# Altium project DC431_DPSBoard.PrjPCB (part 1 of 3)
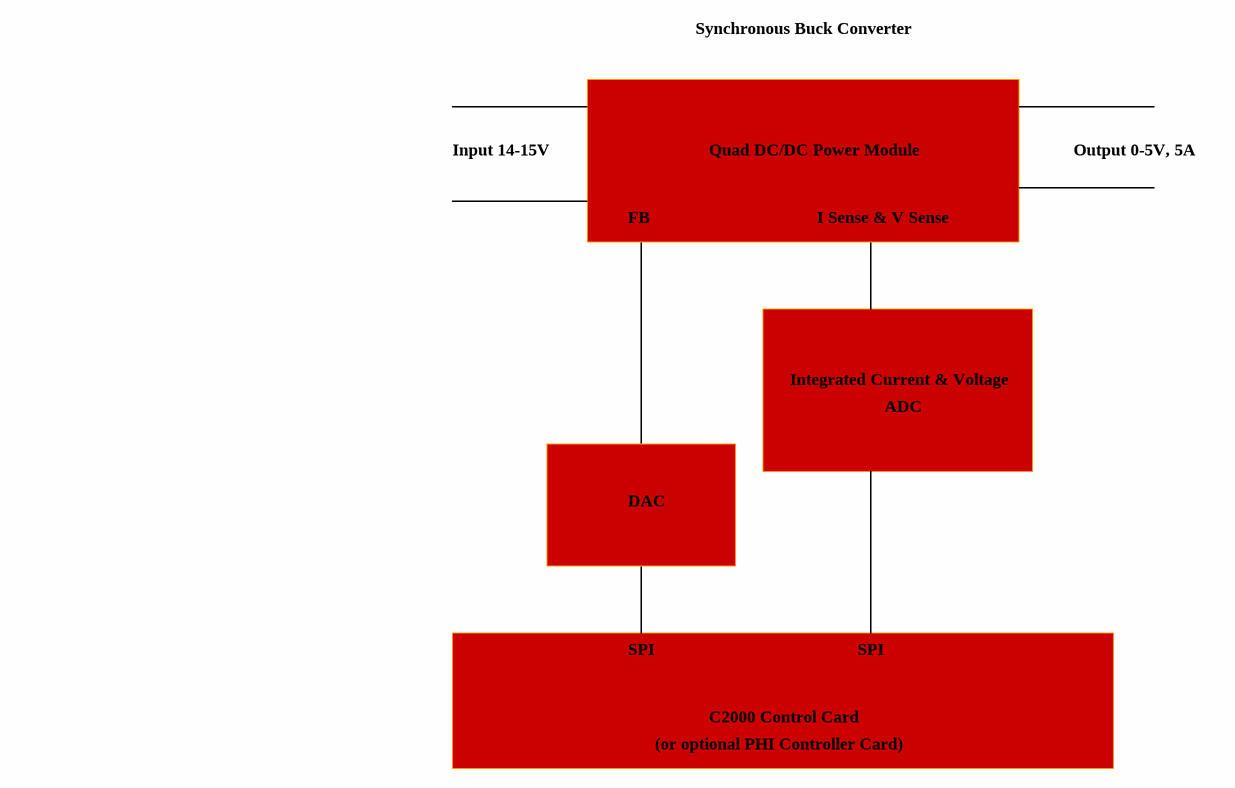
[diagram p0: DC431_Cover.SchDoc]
CopyrightYear: 2025; PCB_Layout: Samiha Sharif; PCB_Rev: A; PRJ_Customer: Public Release; PRJ_Engineer: Samiha Sharif; PRJ_Number: DC431; PRJ_Title: DPS Board; SCH_Rev: A; TechSupport: http://www.ti.com/support; TID: N/A
9 sheets, 455 parts. Net scope: hierarchical (ports join the sheet entries above them; power ports are global).
Board file: SR130E1_pcb.PcbDoc
Sheets:
  DC431_Cover.SchDoc
  DC431_TopLevel.SchDoc
    U_DC431_BiasPower = DC431_BiasPower.SchDoc
    U_DC431_Hardware = DC431_Hardware.SchDoc
    U_DC431_Relay = DC431_Relay.SchDoc
    U_DC431_ADC = DC431_ADC.SchDoc
    U_DC431_Controller = DC431_Controller.SchDoc
    U_DC431_PowerStage = DC431_PowerStage.SchDoc
    U_DC431_Clamp_Optional = DC431_Clamp_Optional.SchDoc

## Sheet DC431_Cover.SchDoc
size 431 x 279 mm; Date: Not shown in title block; ApprovedBy: Not shown in title block; CheckedBy: Not shown in title block; Author: Not shown in title block; CompanyName: Not shown in title block; Engineer: Not shown in title block; Organization: Not shown in title block; Address1: Not shown in title block; Address2: Not shown in title block; Address3: Not shown in title block; Address4: Not shown in title block; DocumentNumber: 1; Revision: Use project parameter SCH_Rev; SheetNumber: 1; SheetTotal: 9; PageSetup: Record=PageOptions¦CenterHorizontal=True¦CenterVertical=True¦PrintScale=1.00¦XCorrection=1.00¦YCorrection=1.00¦PrintKind=0¦BorderSize=5000000¦LeftOffset=0¦BottomOffset=0¦Orientation=2¦PaperLength=1000¦PaperWidth=1000¦Scale=100¦PaperSource=15¦PrintQuality=600¦MediaType=1¦DitherType=10¦PaperKind=Letter¦PrintScaleMode=1

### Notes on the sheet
- Synchronous Buck Converter
- Input 14-15V
- Quad DC/DC Power Module
- Power Stage
- Output 0-5V, 5A
- FB
- I Sense & V Sense
- Integrated Current & Voltage
- ADC
- DAC
- SPI
- (or optional PHI Controller Card)
- C2000 Control Card

## Sheet DC431_TopLevel.SchDoc
size 431 x 279 mm; Date: Not shown in title block; ApprovedBy: Not shown in title block; CheckedBy: Not shown in title block; Author: Not shown in title block; CompanyName: Not shown in title block; DrawnBy: Battery test; Engineer: Not shown in title block; Organization: Not shown in title block; Address1: Not shown in title block; Address2: Not shown in title block; Address3: Not shown in title block; Address4: Not shown in title block; DocumentNumber: 2; Revision: Use project parameter SCH_Rev; SheetNumber: 2; SheetTotal: 9; PageSetup: Record=PageOptions¦CenterHorizontal=True¦CenterVertical=True¦PrintScale=1.00¦XCorrection=1.00¦YCorrection=1.00¦PrintKind=0¦BorderSize=5000000¦LeftOffset=0¦BottomOffset=0¦Orientation=2¦PaperLength=1000¦PaperWidth=1000¦Scale=100¦PaperSource=15¦PrintQuality=600¦MediaType=1¦DitherType=10¦PaperKind=Letter¦PrintScaleMode=1
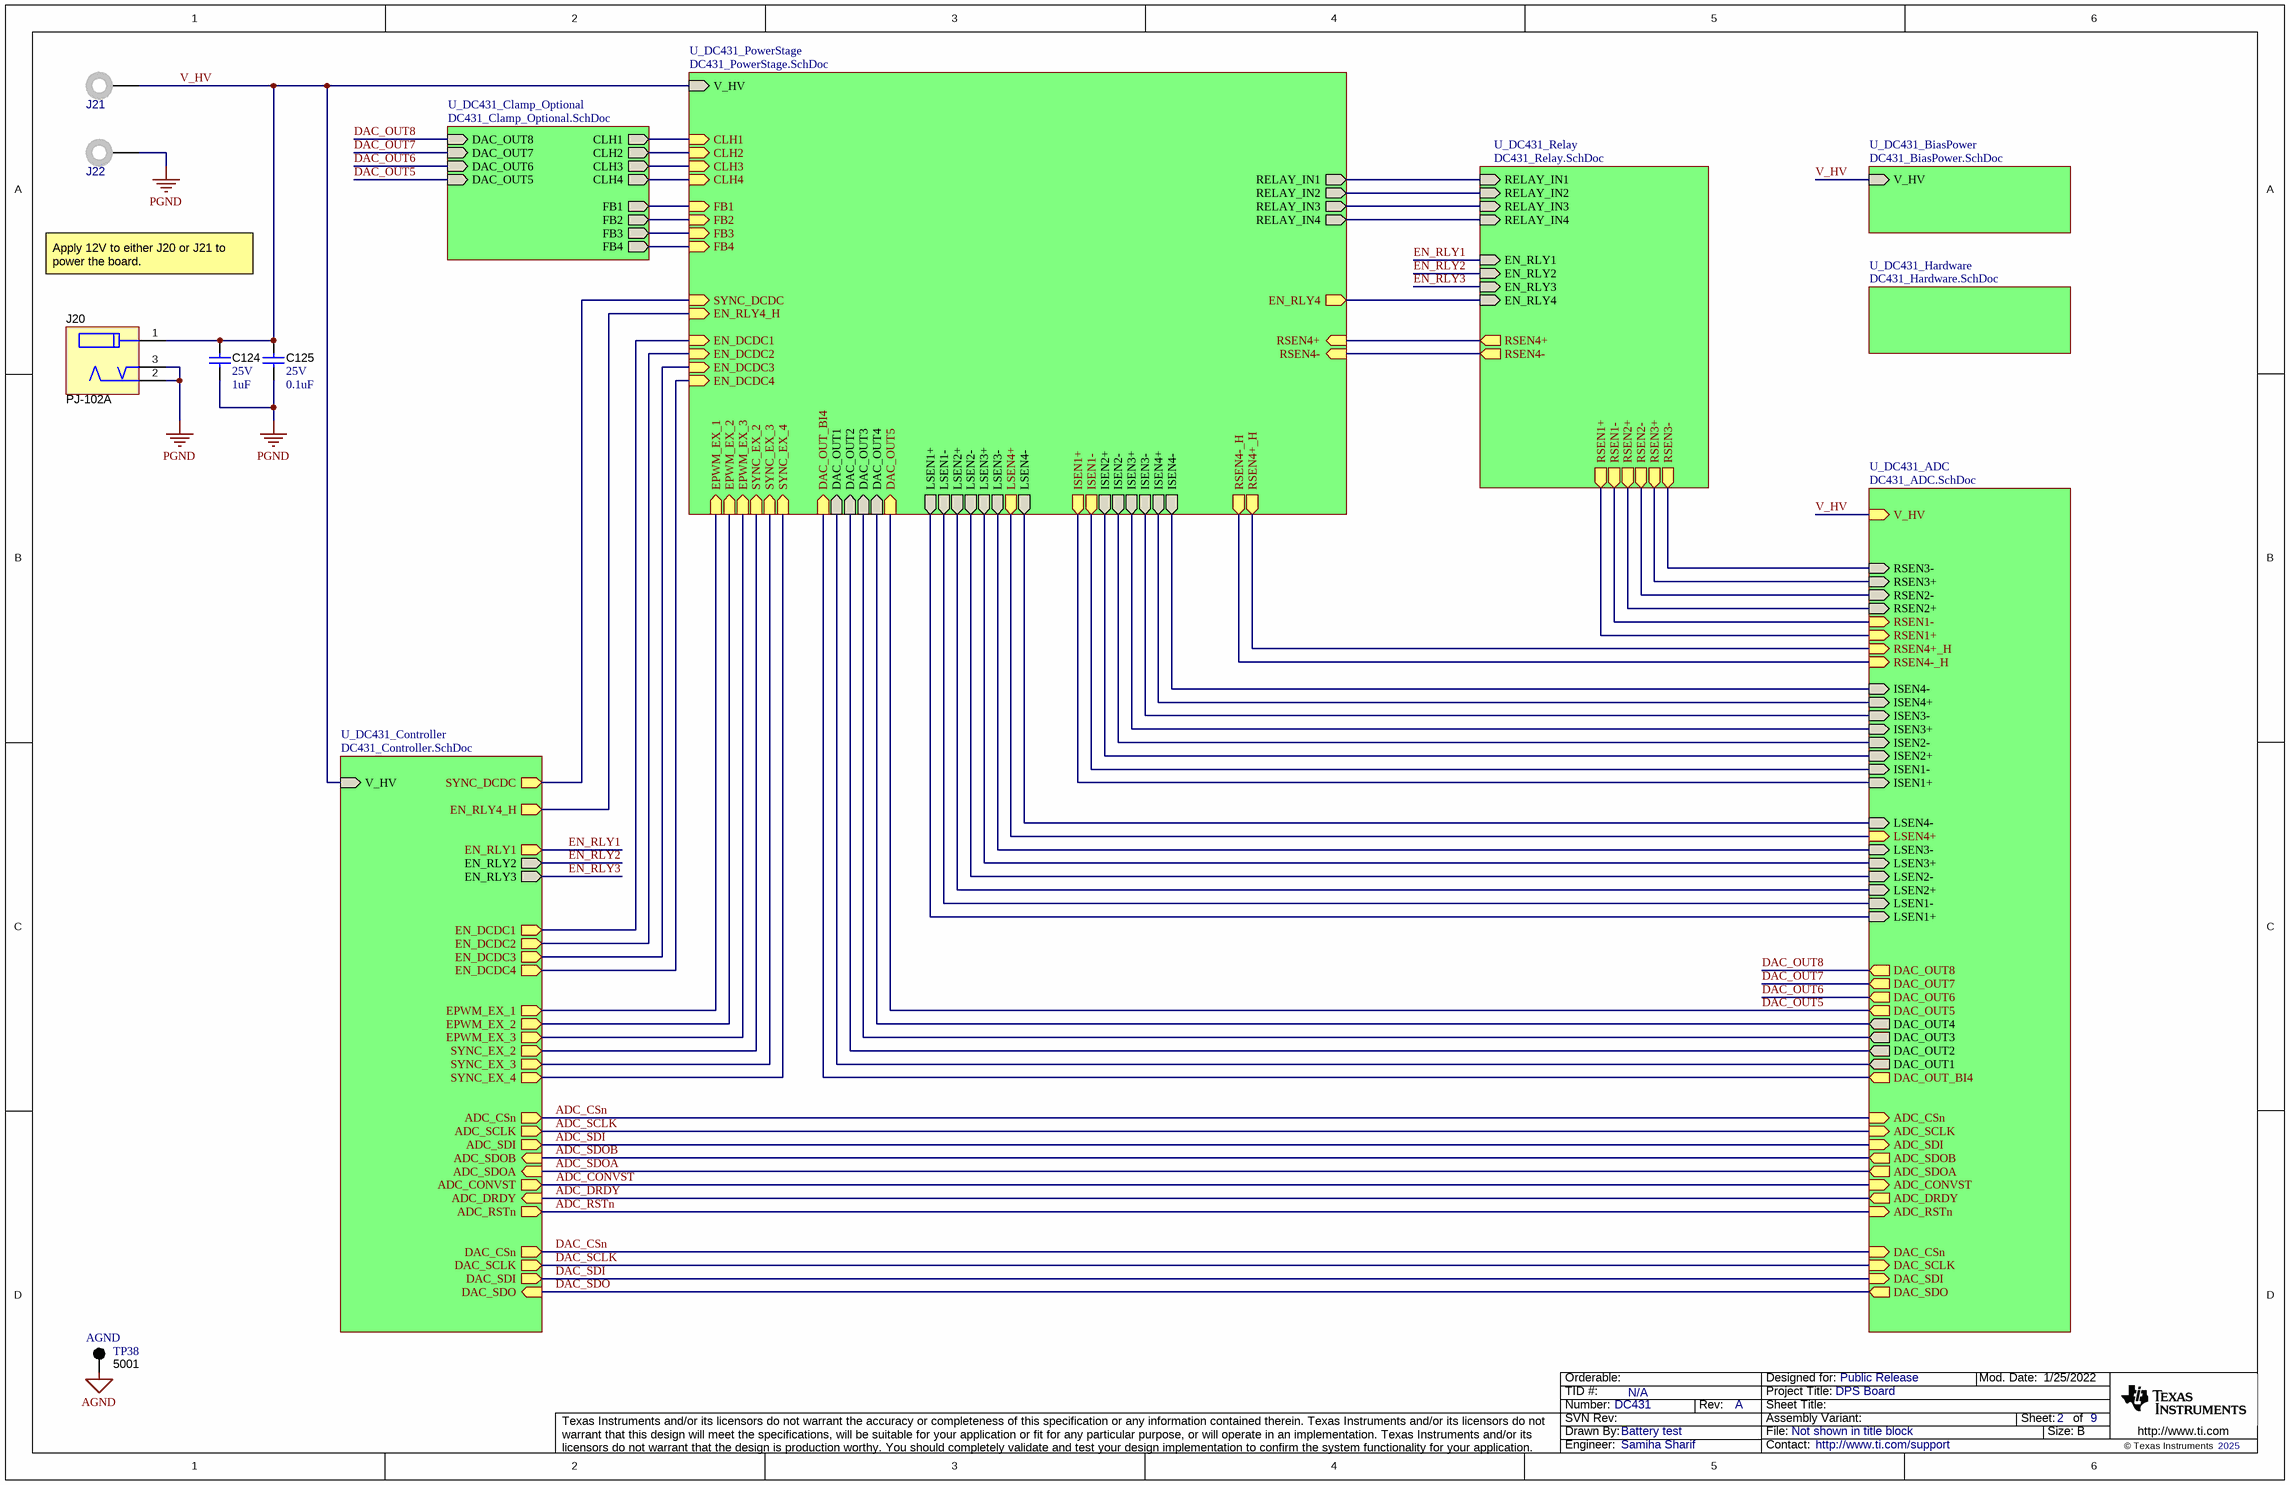
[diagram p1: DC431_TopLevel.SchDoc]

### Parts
C124  VDC_V: 25V  ValueDisplayed: 1uF  [0603S]  (hidden comment: C1608X7R1E105K080AB)
C125  VDC_V: 25V  ValueDisplayed: 0.1uF  [0402S]  (hidden comment: GRM155R71E104KE14D)
J20  PJ-102A  [CONN_PJ-102A]
J21  CMP-0055165-2  [Keystone_575-4]  (value not drawn)
J22  CMP-0055165-2  [Keystone_575-4]  (value not drawn)
TP38  5001  [Keystone5001]

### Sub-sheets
U_DC431_ADC = DC431_ADC.SchDoc: RSEN2+ (in), RSEN2- (in), RSEN3+ (in), RSEN3- (in), DAC_OUT2 (out), DAC_OUT3 (out), DAC_OUT4 (out), ISEN2- (in), ISEN2+ (in), ISEN3- (in), ISEN3+ (in), ISEN4- (in), ISEN4+ (in), LSEN2+ (in), LSEN3+ (in), LSEN2- (in), ISEN1- (in), ISEN1+ (in), LSEN1+ (in), DAC_OUT1 (out), LSEN1- (in), LSEN3- (in), LSEN4- (in), DAC_OUT6 (out), DAC_OUT7 (out), DAC_OUT8 (out), DAC_OUT5 (out), ADC_SCLK (in), ADC_CSn (in), ADC_CONVST (in), ADC_SDI (in), ADC_SDOA (out), ADC_RSTn (in), ADC_DRDY (out), ADC_SDOB (out), DAC_SCLK (in), DAC_CSn (in), DAC_SDI (in), DAC_SDO (out), V_HV (in), RSEN4-_H (in), RSEN4+_H (in), RSEN1- (in), RSEN1+ (in), DAC_OUT_BI4 (out), LSEN4+ (in)
U_DC431_BiasPower = DC431_BiasPower.SchDoc: V_HV (in)
U_DC431_Clamp_Optional = DC431_Clamp_Optional.SchDoc: DAC_OUT5 (in), DAC_OUT7 (in), DAC_OUT6 (in), DAC_OUT8 (in), CLH1 (out), CLH2 (out), CLH3 (out), CLH4 (out), FB1 (out), FB2 (out), FB3 (out), FB4 (out)
U_DC431_Controller = DC431_Controller.SchDoc: EN_RLY2 (out), EN_RLY3 (out), V_HV (in), ADC_SCLK (out), ADC_RSTn (out), ADC_CONVST (out), ADC_DRDY (in), ADC_SDOA (in), ADC_CSn (out), ADC_SDI (out), DAC_SCLK (out), DAC_CSn (out), DAC_SDI (out), DAC_SDO (in), ADC_SDOB (in), EN_DCDC1 (out), EN_DCDC2 (out), EN_DCDC3 (out), EN_DCDC4 (out), SYNC_DCDC (out), EPWM_EX_1 (out), EPWM_EX_2 (out), EPWM_EX_3 (out), SYNC_EX_2 (out), SYNC_EX_3 (out), SYNC_EX_4 (out), EN_RLY1 (out), EN_RLY4_H (out)
U_DC431_Hardware = DC431_Hardware.SchDoc: no entries
U_DC431_PowerStage = DC431_PowerStage.SchDoc: V_HV (in), DAC_OUT2 (in), DAC_OUT3 (in), DAC_OUT4 (in), ISEN2- (out), ISEN2+ (out), ISEN3- (out), ISEN3+ (out), ISEN4- (out), ISEN4+ (out), LSEN2+ (out), LSEN3+ (out), LSEN2- (out), LSEN3- (out), LSEN4- (out), RELAY_IN1 (out), RELAY_IN2 (out), RELAY_IN3 (out), RELAY_IN4 (out), LSEN1+ (out), DAC_OUT1 (in), LSEN1- (out), CLH1 (in), CLH2 (in), CLH3 (in), CLH4 (in), FB1 (in), FB2 (in), FB3 (in), FB4 (in), EN_DCDC2 (in), SYNC_DCDC (in), EN_DCDC3 (in), EN_DCDC4 (in), SYNC_EX_2 (in), SYNC_EX_3 (in), SYNC_EX_4 (in), EPWM_EX_1 (in), EPWM_EX_2 (in), EPWM_EX_3 (in), DAC_OUT5 (in), LSEN4+ (out), RSEN4- (in), RSEN4+ (in), EN_RLY4 (out), RSEN4+_H (out), RSEN4-_H (out), EN_RLY4_H (in), DAC_OUT_BI4 (in), ISEN1- (out), ISEN1+ (out), EN_DCDC1 (in)
U_DC431_Relay = DC431_Relay.SchDoc: RELAY_IN1 (in), EN_RLY1 (in), RELAY_IN2 (in), EN_RLY2 (in), RELAY_IN3 (in), EN_RLY3 (in), RELAY_IN4 (in), EN_RLY4 (in), RSEN1+ (out), RSEN1- (out), RSEN2+ (out), RSEN2- (out), RSEN3+ (out), RSEN3- (out), RSEN4+ (out), RSEN4- (out)

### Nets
AGND: TP38.1
PGND: C124.2 C125.2 J20.2 J20.3 J22.1
ADC_CONVST: sheet U_DC431_ADC/ADC_CONVST, sheet U_DC431_Controller/ADC_CONVST
ADC_CSn: sheet U_DC431_ADC/ADC_CSn, sheet U_DC431_Controller/ADC_CSn
ADC_DRDY: sheet U_DC431_ADC/ADC_DRDY, sheet U_DC431_Controller/ADC_DRDY
ADC_RSTn: sheet U_DC431_ADC/ADC_RSTn, sheet U_DC431_Controller/ADC_RSTn
ADC_SCLK: sheet U_DC431_ADC/ADC_SCLK, sheet U_DC431_Controller/ADC_SCLK
ADC_SDI: sheet U_DC431_ADC/ADC_SDI, sheet U_DC431_Controller/ADC_SDI
ADC_SDOA: sheet U_DC431_ADC/ADC_SDOA, sheet U_DC431_Controller/ADC_SDOA
ADC_SDOB: sheet U_DC431_ADC/ADC_SDOB, sheet U_DC431_Controller/ADC_SDOB
AINM1: sheet U_DC431_Relay/RSEN1-, sheet U_DC431_ADC/RSEN1-
AINM2: sheet U_DC431_Relay/RSEN2-, sheet U_DC431_ADC/RSEN2-
AINM3: sheet U_DC431_Relay/RSEN3-, sheet U_DC431_ADC/RSEN3-
AINM4: sheet U_DC431_ADC/RSEN4-_H, sheet U_DC431_PowerStage/RSEN4-_H
AINM5: sheet U_DC431_ADC/ISEN1-, sheet U_DC431_PowerStage/ISEN1-
AINM6: sheet U_DC431_ADC/ISEN2-, sheet U_DC431_PowerStage/ISEN2-
AINM7: sheet U_DC431_ADC/ISEN3-, sheet U_DC431_PowerStage/ISEN3-
AINM8: sheet U_DC431_ADC/ISEN4-, sheet U_DC431_PowerStage/ISEN4-
AINM9: sheet U_DC431_ADC/LSEN1-, sheet U_DC431_PowerStage/LSEN1-
AINM10: sheet U_DC431_ADC/LSEN2-, sheet U_DC431_PowerStage/LSEN2-
AINM11: sheet U_DC431_ADC/LSEN3-, sheet U_DC431_PowerStage/LSEN3-
AINM12: sheet U_DC431_ADC/LSEN4-, sheet U_DC431_PowerStage/LSEN4-
AINP1: sheet U_DC431_Relay/RSEN1+, sheet U_DC431_ADC/RSEN1+
AINP2: sheet U_DC431_Relay/RSEN2+, sheet U_DC431_ADC/RSEN2+
AINP3: sheet U_DC431_Relay/RSEN3+, sheet U_DC431_ADC/RSEN3+
AINP4: sheet U_DC431_ADC/RSEN4+_H, sheet U_DC431_PowerStage/RSEN4+_H
AINP5: sheet U_DC431_ADC/ISEN1+, sheet U_DC431_PowerStage/ISEN1+
AINP6: sheet U_DC431_ADC/ISEN2+, sheet U_DC431_PowerStage/ISEN2+
AINP7: sheet U_DC431_ADC/ISEN3+, sheet U_DC431_PowerStage/ISEN3+
AINP8: sheet U_DC431_ADC/ISEN4+, sheet U_DC431_PowerStage/ISEN4+
AINP9: sheet U_DC431_ADC/LSEN1+, sheet U_DC431_PowerStage/LSEN1+
AINP10: sheet U_DC431_ADC/LSEN2+, sheet U_DC431_PowerStage/LSEN2+
AINP11: sheet U_DC431_ADC/LSEN3+, sheet U_DC431_PowerStage/LSEN3+
AINP12: sheet U_DC431_ADC/LSEN4+, sheet U_DC431_PowerStage/LSEN4+
COMP1: sheet U_DC431_PowerStage/CLH1, sheet U_DC431_Clamp_Optional/CLH1
COMP2: sheet U_DC431_PowerStage/CLH2, sheet U_DC431_Clamp_Optional/CLH2
COMP3: sheet U_DC431_PowerStage/CLH3, sheet U_DC431_Clamp_Optional/CLH3
COMP4: sheet U_DC431_PowerStage/CLH4, sheet U_DC431_Clamp_Optional/CLH4
DAC_CH4: sheet U_DC431_ADC/DAC_OUT4, sheet U_DC431_PowerStage/DAC_OUT4
DAC_CSn: sheet U_DC431_ADC/DAC_CSn, sheet U_DC431_Controller/DAC_CSn
DAC_OUT1: sheet U_DC431_ADC/DAC_OUT1, sheet U_DC431_PowerStage/DAC_OUT1
DAC_OUT2: sheet U_DC431_ADC/DAC_OUT2, sheet U_DC431_PowerStage/DAC_OUT2
DAC_OUT3: sheet U_DC431_ADC/DAC_OUT3, sheet U_DC431_PowerStage/DAC_OUT3
DAC_OUT5: sheet U_DC431_ADC/DAC_OUT5, sheet U_DC431_PowerStage/DAC_OUT5, sheet U_DC431_Clamp_Optional/DAC_OUT5
DAC_OUT6: sheet U_DC431_ADC/DAC_OUT6, sheet U_DC431_Clamp_Optional/DAC_OUT6
DAC_OUT7: sheet U_DC431_ADC/DAC_OUT7, sheet U_DC431_Clamp_Optional/DAC_OUT7
DAC_OUT8: sheet U_DC431_ADC/DAC_OUT8, sheet U_DC431_Clamp_Optional/DAC_OUT8
DAC_OUT_BI4: sheet U_DC431_ADC/DAC_OUT_BI4, sheet U_DC431_PowerStage/DAC_OUT_BI4
DAC_SCLK: sheet U_DC431_ADC/DAC_SCLK, sheet U_DC431_Controller/DAC_SCLK
DAC_SDI: sheet U_DC431_ADC/DAC_SDI, sheet U_DC431_Controller/DAC_SDI
DAC_SDO: sheet U_DC431_ADC/DAC_SDO, sheet U_DC431_Controller/DAC_SDO
EN_DCDC1: sheet U_DC431_Controller/EN_DCDC1, sheet U_DC431_PowerStage/EN_DCDC1
EN_DCDC2: sheet U_DC431_Controller/EN_DCDC2, sheet U_DC431_PowerStage/EN_DCDC2
EN_DCDC3: sheet U_DC431_Controller/EN_DCDC3, sheet U_DC431_PowerStage/EN_DCDC3
EN_DCDC4: sheet U_DC431_Controller/EN_DCDC4, sheet U_DC431_PowerStage/EN_DCDC4
EN_RLY1: sheet U_DC431_Relay/EN_RLY1, sheet U_DC431_Controller/EN_RLY1
EN_RLY2: sheet U_DC431_Relay/EN_RLY2, sheet U_DC431_Controller/EN_RLY2
EN_RLY3: sheet U_DC431_Relay/EN_RLY3, sheet U_DC431_Controller/EN_RLY3
EN_RLY4: sheet U_DC431_Relay/EN_RLY4, sheet U_DC431_PowerStage/EN_RLY4
EN_RLY4_H: sheet U_DC431_Controller/EN_RLY4_H, sheet U_DC431_PowerStage/EN_RLY4_H
EPWM_EX_1: sheet U_DC431_Controller/EPWM_EX_1, sheet U_DC431_PowerStage/EPWM_EX_1
EPWM_EX_2: sheet U_DC431_Controller/EPWM_EX_2, sheet U_DC431_PowerStage/EPWM_EX_2
EPWM_EX_3: sheet U_DC431_Controller/EPWM_EX_3, sheet U_DC431_PowerStage/EPWM_EX_3
FB1: sheet U_DC431_PowerStage/FB1, sheet U_DC431_Clamp_Optional/FB1
FB2: sheet U_DC431_PowerStage/FB2, sheet U_DC431_Clamp_Optional/FB2
FB3: sheet U_DC431_PowerStage/FB3, sheet U_DC431_Clamp_Optional/FB3
FB4: sheet U_DC431_PowerStage/FB4, sheet U_DC431_Clamp_Optional/FB4
RELAY_IN1: sheet U_DC431_Relay/RELAY_IN1, sheet U_DC431_PowerStage/RELAY_IN1
RELAY_IN2: sheet U_DC431_Relay/RELAY_IN2, sheet U_DC431_PowerStage/RELAY_IN2
RELAY_IN3: sheet U_DC431_Relay/RELAY_IN3, sheet U_DC431_PowerStage/RELAY_IN3
RELAY_IN4: sheet U_DC431_Relay/RELAY_IN4, sheet U_DC431_PowerStage/RELAY_IN4
REMSN4: sheet U_DC431_Relay/RSEN4-, sheet U_DC431_PowerStage/RSEN4-
REMSP4: sheet U_DC431_Relay/RSEN4+, sheet U_DC431_PowerStage/RSEN4+
SYNC_DCDC: sheet U_DC431_Controller/SYNC_DCDC, sheet U_DC431_PowerStage/SYNC_DCDC
SYNC_EX_2: sheet U_DC431_Controller/SYNC_EX_2, sheet U_DC431_PowerStage/SYNC_EX_2
SYNC_EX_3: sheet U_DC431_Controller/SYNC_EX_3, sheet U_DC431_PowerStage/SYNC_EX_3
SYNC_EX_4: sheet U_DC431_Controller/SYNC_EX_4, sheet U_DC431_PowerStage/SYNC_EX_4
V_HV: C124.1 C125.1 J20.1 J21.1 ; sheet U_DC431_BiasPower/V_HV, sheet U_DC431_ADC/V_HV, sheet U_DC431_Controller/V_HV, sheet U_DC431_PowerStage/V_HV

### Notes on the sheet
- Apply 12V to either J20 or J21 to power the board.
- (near TP38) AGND

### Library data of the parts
C124 = CMP-0007040-4: CAP, CERM, 1 uF, 25 V, +/- 10%, X7R, 0603; Manufacturer: TDK; TaMin_C: -55°C; Polarized: N; SizeAreaWB_mm2: 4.68; U/M: EA; Value: 1uF; TaMax_C: 125°C; SizeZ_mm: 1; SizeX_mm: 1.6; SizeY_mm: 0.8; Cap_Case: 0603; SizeArea_mm2: 1.28; Cap_F: 1µF; AEC Category: Q200; Value1: Unknown
C125 = CMP-0006659-2: CAP, CERM, 0.1 uF, 25 V, +/- 10%, X7R, 0402; Manufacturer: MuRata; TaMin_C: -55°C; Polarized: N; SizeAreaWB_mm2: 3; U/M: EA; Value: 0.1uF; TaMax_C: 125°C; SizeZ_mm: 0.6; SizeX_mm: 1; SizeY_mm: 0.5; Cap_Case: 0402; Cap_F: 100nF; AEC Category: Q200; Value1: Unknown
J20 = CMP-0055462-1: Connector, DC Jack 2.1X5.5 mm, TH; Manufacturer: CUI Inc.; CT: FALSE; Green_REACh: Incomplete; Green_Lifecycle: Not Set
J21 J22 = CMP-0055165-2: Standard Banana Jack, Uninsulated, 5.5mm; PartNumber: 575-4; Manufacturer: Keystone; CT: TRUE; Green_REACh: Passed; CNHeader: FALSE; Green_Lifecycle: Active
TP38 = CMP-0055138-2: Test Point, Miniature, Black, TH; Manufacturer: Keystone Electronics; CNHeader: FALSE; ContactFinish: Silver; Green_REACh: Passed; Green_Lifecycle: Active; CT: TRUE

## Sheet DC431_BiasPower.SchDoc
size 431 x 279 mm; Date: Not shown in title block; ApprovedBy: Not shown in title block; CheckedBy: Not shown in title block; Author: Not shown in title block; CompanyName: Not shown in title block; DrawnBy: Battery test; Engineer: Not shown in title block; Organization: Not shown in title block; Address1: Not shown in title block; Address2: Not shown in title block; Address3: Not shown in title block; Address4: Not shown in title block; DocumentNumber: 7; Revision: Use project parameter SCH_Rev; SheetNumber: 8; SheetTotal: 9; PageSetup: Record=PageOptions¦CenterHorizontal=True¦CenterVertical=True¦PrintScale=1.00¦XCorrection=1.00¦YCorrection=1.00¦PrintKind=0¦BorderSize=5000000¦LeftOffset=0¦BottomOffset=0¦Orientation=2¦PaperLength=1000¦PaperWidth=1000¦Scale=100¦PaperSource=15¦PrintQuality=600¦MediaType=1¦DitherType=10¦PaperKind=Letter¦PrintScaleMode=1
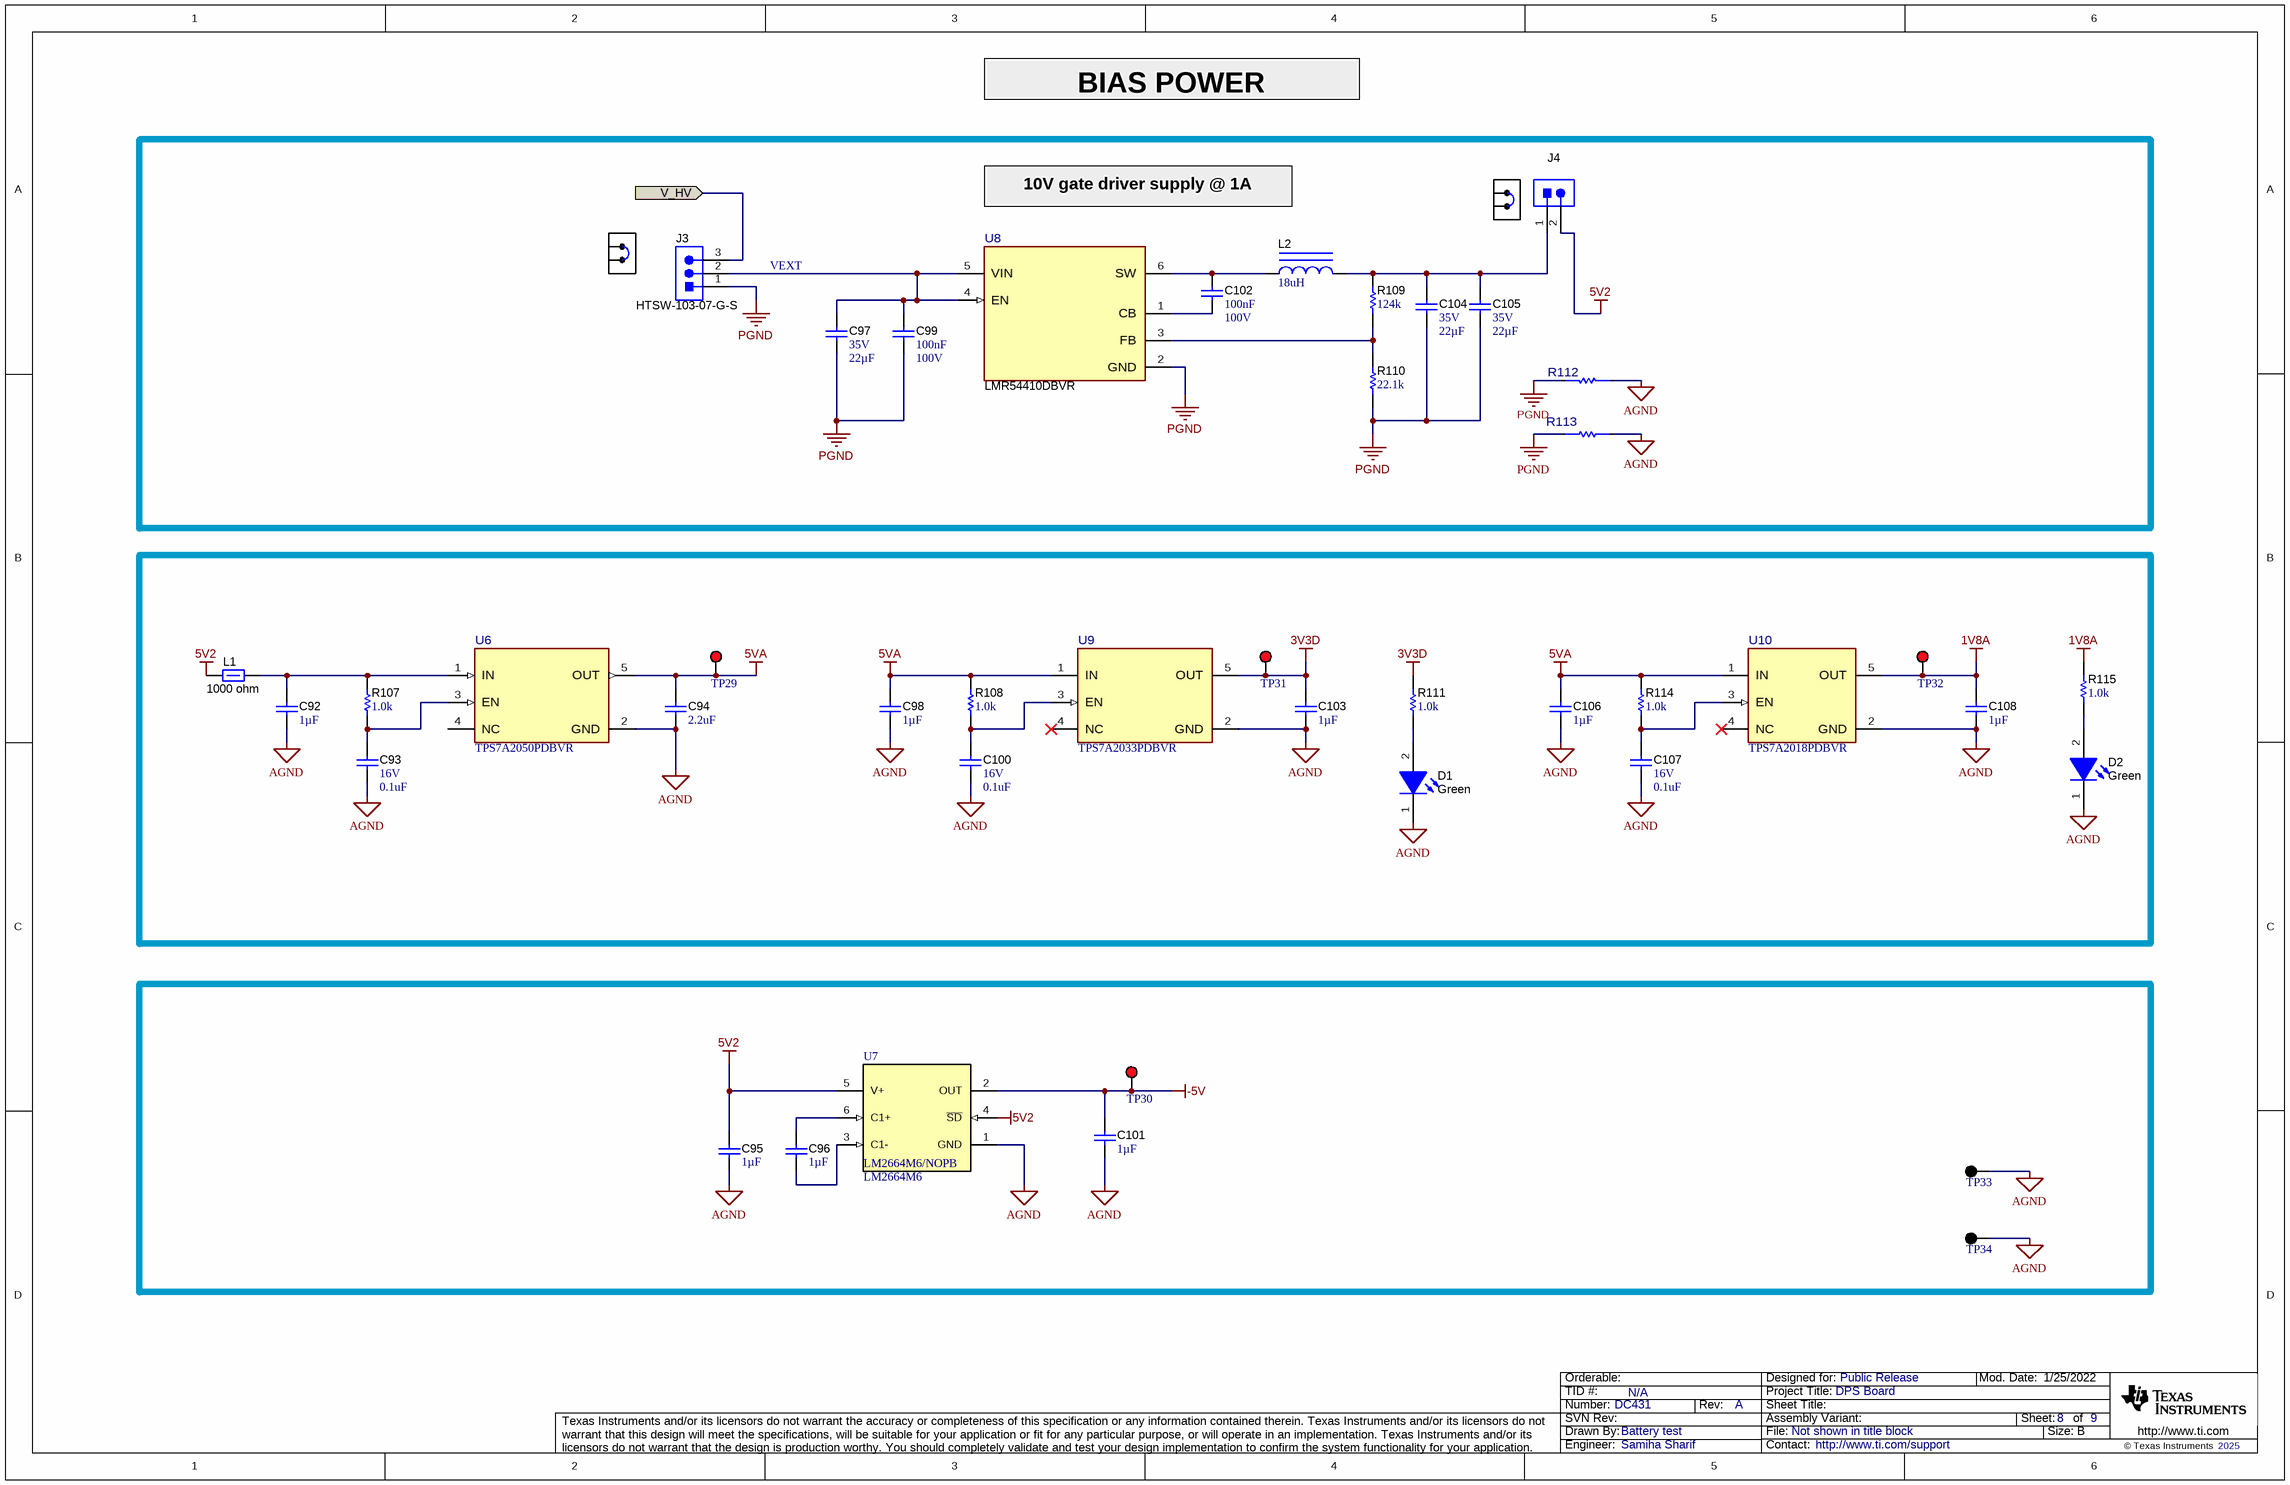
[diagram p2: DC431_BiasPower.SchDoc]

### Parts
C92  ValueDisplayed: 1µF  [0603S]  (hidden comment: CGA3E1X7R1E105K080AC)
C93  VDC_V: 16V  ValueDisplayed: 0.1uF  [0402S]  (hidden comment: GRM155R61C104KA88D)
C94  ValueDisplayed: 2.2uF  [0603S]  (hidden comment: F381A225MMA)
C95  ValueDisplayed: 1µF  [0603S]  (hidden comment: CGA3E1X7R1E105K080AC)
C96  ValueDisplayed: 1µF  [0603S]  (hidden comment: CGA3E1X7R1E105K080AC)
C97  VDC_V: 35V  ValueDisplayed: 22µF  [1210]  (hidden comment: GMK325BJ226MM-P)
C98  ValueDisplayed: 1µF  [0603S]  (hidden comment: CGA3E1X7R1E105K080AC)
C99  Cap_F: 100nF  VDC_V: 100V  [0603S]  (hidden comment: GRM188R72A104KA35D)
C100  VDC_V: 16V  ValueDisplayed: 0.1uF  [0402S]  (hidden comment: GRM155R61C104KA88D)
C101  ValueDisplayed: 1µF  [0603S]  (hidden comment: CGA3E1X7R1E105K080AC)
C102  Cap_F: 100nF  VDC_V: 100V  [0603S]  (hidden comment: GRM188R72A104KA35D)
C103  ValueDisplayed: 1µF  [0603S]  (hidden comment: CGA3E1X7R1E105K080AC)
C104  VDC_V: 35V  ValueDisplayed: 22µF  [1210]  (hidden comment: GMK325BJ226MM-P)
C105  VDC_V: 35V  ValueDisplayed: 22µF  [1210]  (hidden comment: GMK325BJ226MM-P)
C106  ValueDisplayed: 1µF  [0603S]  (hidden comment: CGA3E1X7R1E105K080AC)
C107  VDC_V: 16V  ValueDisplayed: 0.1uF  [0402S]  (hidden comment: GRM155R61C104KA88D)
C108  ValueDisplayed: 1µF  [0603S]  (hidden comment: CGA3E1X7R1E105K080AC)
D1  value Green  [WL-SMCW_GREEN]  (hidden comment: 150060VS75000)
D2  value Green  [WL-SMCW_GREEN]  (hidden comment: 150060VS75000)
J3  HTSW-103-07-G-S  [Samtec_HTSW-103-07-G-S]
J4  HTSW-102-07-G-S  [Samtec_HTSW-102-07-G-S]  (value not drawn)
L1  value 1000 ohm  [1806_HighSpeed]  (hidden comment: BLM41PG102SN1L)
L2  ValueDisplayed: 18uH  [LPS5015]  (hidden comment: LPS5015-183MLB)
R107  ValueDisplayed: 1.0k  [0603S]  (hidden comment: CRCW06031K00JNEA)
R108  ValueDisplayed: 1.0k  [0603S]  (hidden comment: CRCW06031K00JNEA)
R109  ValueDisplayed: 124k  [0402S]  (hidden comment: CRCW0402124KFKED)
R110  ValueDisplayed: 22.1k  [0402S]  (hidden comment: CRCW040222K1FKED)
R111  ValueDisplayed: 1.0k  [0603S]  (hidden comment: CRCW06031K00JNEA)
R112  CRCW12060000Z0EAC  [FP-CRCW12060000Z0EAC_1206-MFG]  (value not drawn)
R113  CRCW12060000Z0EAC  [FP-CRCW12060000Z0EAC_1206-MFG]  (value not drawn)
R114  ValueDisplayed: 1.0k  [0603S]  (hidden comment: CRCW06031K00JNEA)
R115  ValueDisplayed: 1.0k  [0603S]  (hidden comment: CRCW06031K00JNEA)
SH-J1  60900213421  [Wurth_60900213421]  (value not drawn)
SH-J2  60900213421  [Wurth_60900213421]  (value not drawn)
TP29  5000  [Keystone5000]  (value not drawn)
TP30  5000  [Keystone5000]  (value not drawn)
TP31  5000  [Keystone5000]  (value not drawn)
TP32  5000  [Keystone5000]  (value not drawn)
TP33  5001  [Keystone5001]  (value not drawn)
TP34  5001  [Keystone5001]  (value not drawn)
U6  TPS7A2050PDBVR  [DBV0005A-MFG]
U7  LM2664M6  PartNumber: LM2664M6/NOPB  [DBV0006A_N]
U8  LMR54410DBVR  [DBV0006A-MFG]
U9  TPS7A2033PDBVR  [DBV0005A-MFG]
U10  TPS7A2018PDBVR  [DBV0005A-MFG]

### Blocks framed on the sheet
VEXT: C97 C99 C102 C104 C105 J3 J4 L2 R109 R110 R112 R113 SH-J1 SH-J2 U8

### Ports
V_HV (in)

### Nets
1V8A: C108.1 R115.2 TP32.1 U10.5(OUT)
3V3D: C103.1 R111.2 TP31.1 U9.5(OUT)
5V2: C95.2 J4.2 L1.1 U7.4(~{SD}) U7.5(V+)
5VA: C94.1 C98.1 C106.1 R108.1 R114.1 TP29.1 U6.5(OUT) U9.1(IN) U10.1(IN)
-5V: C101.2 TP30.1 U7.2(OUT)
AGND: C92.2 C93.1 C94.2 C95.1 C98.2 C100.1 C101.1 C103.2 C106.2 C107.1 C108.2 D1.1(K) D2.1(K) R112.1 R113.2 TP33.1 TP34.1 U6.2(GND) U7.1(GND) U9.2(GND) U10.2(GND)
PGND: C97.2 C99.2 C104.2 C105.2 J3.1 R110.1 R112.2 R113.1 U8.2(GND)
V_HV: J3.3 ; port V_HV
NetC92_1: C92.1 L1.2 R107.1 U6.1(IN)
NetC93_2: C93.2 R107.2 U6.3(EN)
NetC96_1: C96.1 U7.3(C1-)
NetC96_2: C96.2 U7.6(C1+)
NetC97_1: C97.1 C99.1 J3.2 U8.4(EN) U8.5(VIN)
NetC100_2: C100.2 R108.2 U9.3(EN)
NetC102_1: C102.1 L2.1 U8.6(SW)
NetC102_2: C102.2 U8.1(CB)
NetC104_1: C104.1 C105.1 J4.1 L2.2 R109.2
NetC107_2: C107.2 R114.2 U10.3(EN)
NetD1_2: D1.2(A) R111.1
NetD2_2: D2.2(A) R115.1
NetR109_1: R109.1 R110.2 U8.3(FB)

Not connected (* = marked no-connect by the designer): U6 4(NC); U9 4(NC)*; U10 4(NC)*

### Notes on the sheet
- BIAS POWER
- 10V gate driver supply @ 1A

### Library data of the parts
C92 C95 C96 C98 C101 C103 C106 C108 = CMP-0076705-3: CAP, CERM, 1 µF, 25 V,+/- 10%, X7R, AEC-Q200 Grade 1, 0603; Manufacturer: TDK; Polarized: N; Value: 1uF; U/M: EA; VDC_V: 25V; TaMin_C: -55°C; TaMax_C: 125°C; Cap_Case: 1.6x0.8x0.8mm; SizeAreaWB_mm2: 4.68; SizeArea_mm2: 1.28; AEC Qualified: Y; AEC Category: Q200; SizeZ_mm: 1.0; AEC Grade: 1; SizeY_mm: 0.8; SizeX_mm: 1.6
C93 C100 C107 = CMP-0006591-2: CAP, CERM, 0.1 uF, 16 V, +/- 10%, X5R, 0402; Manufacturer: MuRata; TaMin_C: -55°C; Polarized: N; SizeAreaWB_mm2: 3; Value1: Unknown; U/M: EA; Value: 0.1uF; TaMax_C: 85°C; SizeZ_mm: 0.6; SizeX_mm: 1; SizeY_mm: 0.5; Cap_Case: 0402; Cap_F: 100nF; AEC Category: Q200
C94 = CMP-0076705-3: CAP TANT POLY 2.2UF 10V 0603; Manufacturer: KYOCERA AVX; Polarized: N; U/M: EA; Tolerance_%: 20%; ESR_ohm: 0.2; TempCo: X7R; TaMin_C: -55°C; TaMax_C: 125°C; Cap_Case: 1.6x0.8x0.8mm; SizeAreaWB_mm2: 4.68; SizeArea_mm2: 1.28; AEC Qualified: Y; AEC Category: Q200; SizeZ_mm: 1.0; AEC Grade: 1; SizeY_mm: 0.8; SizeX_mm: 1.6
C97 C104 C105 = CMP-0085817-1: CAP, CERM, 22 µF, 35 V,+/- 20%, X5R, 1210; Manufacturer: Taiyo Yuden; Value: 22uF; SizeZ_mm: 1.35; TaMax_C: 85°C; U/M: EA; SizeAreaWB_mm2: 14.7; SizeX_mm: 3.2; SizeArea_mm2: 8; TaMin_C: -55°C; AEC Qualified: N; SizeY_mm: 2.5; AEC Category: Q200
C99 C102 = CMP-0007469-4: CAP, CERM, 0.1 uF, 100 V, +/- 10%, X7R, 0603; Manufacturer: MuRata; TaMin_C: -55°C; Polarized: N; SizeAreaWB_mm2: 4.68; Value1: Unknown; U/M: EA; Value: 0.1uF; TaMax_C: 125°C; SizeZ_mm: 1; SizeX_mm: 1.6; SizeY_mm: 0.8; Cap_Case: 0603; SizeArea_mm2: 1.28; AEC Category: Q200
D1 D2 = CMP-0002894-2: LED, Green, SMD; Manufacturer: Wurth Elektronik; Type: AlInGaP; Vf_V: 2V; Io_A: 20mA; Value1: W
J3 = CMP-0075484-1: Header, 100mil, 3x1, Gold, TH; Manufacturer: Samtec; Green_REACh: Passed; CT: False; Green_Lifecycle: Active; CNHeader: True
J4 = CMP-0075483-1: Header, 100mil, 2x1, Gold, TH; Manufacturer: Samtec; Green_REACh: Passed; CT: False; Green_Lifecycle: Active; CNHeader: True
L1 = CMP-0003369-1: Ferrite Bead, 1000 ohm @ 100 MHz, 1.5 A, 1806; Manufacturer: MuRata; ZTyp@100MHz_Ohm: 1k; SizeAreaWB_mm2: 14.3; DCR_ohm: 0.09; Value1: 0.09 ohm; Imax_A: 1.5A; SizeZ_mm: 1.85; SizeX_mm: 4.5; SizeY_mm: 1.6; SizeArea_mm2: 7.2
L2 = CMP-0061372-2: Inductor, Shielded Drum Core, Ferrite, 18 uH, 0.8 A, 0.55 ohm, SMD; Manufacturer: Coilcraft; Isat: 0.8A @ 30% inductance drop; Irms: 0.83A @ 40C rise; Green_Lifecycle: Not Set; SizeAreaWB_mm2: 33.64; DCR_ohm: 0.55; Green_REACh: Incomplete; Value: 18uH; Imax_A: 800mA; SizeZ_mm: 1.4; SizeX_mm: 4.8; Value2: 0.8A; SizeArea_mm2: 23.04; Ind_H: 18µH; AEC Category: Q200
R107 R108 R111 R114 R115 = CMP-0025729-4: RES, 1.0 k, 5%, 0.1 W, AEC-Q200 Grade 0, 0603; Manufacturer: Vishay-Dale; Power_W: 100mW; TempCo: 200 ppm/C; Value_Code: 1k00; Value: 1.0k; EIA_Code: E24; Res_ohm: 1k; SizeX_mm: 1.6; SizeY_mm: 0.8; SizeZ_mm: 1; Value2: 0.1W; SizeArea_mm2: 1.28; AEC Qualified: Y; VDC_V: 75V; AEC Category: Q200; AEC Grade: 0
R109 = CMP-0025986-3: RES, 124 k, 1%, 0.063 W, AEC-Q200 Grade 0, 0402; Manufacturer: Vishay-Dale; Power_W: 63mW; TempCo: 100 ppm/C; Value: 124k; EIA_Code: E96; SizeX_mm: 1; SizeY_mm: 0.5; SizeZ_mm: 0.6; Value2: 0.063W; AEC Qualified: Y; VDC_V: 50V; AEC Category: Q200; AEC Grade: 0
R110 = CMP-0026178-2: RES, 22.1 k, 1%, 0.063 W, AEC-Q200 Grade 0, 0402; Manufacturer: Vishay-Dale; Power_W: 63mW; TempCo: 100 ppm/C; Value_Code: 22k1; Value: 22.1k; EIA_Code: E96; SizeX_mm: 1; SizeY_mm: 0.5; SizeZ_mm: 0.6; Value2: 0.063W; AEC Qualified: Y; VDC_V: 50V; AEC Category: Q200; AEC Grade: 0
R112 R113 = CMP-0094724-1: Jumper 0.25W, 1/4W Chip Resistor 1206 (3216 Metric) - Thick Film; Manufacturer: Vishay; Value: 0; Power_W: 250mW; VDC_V: 200V; SizeZ_mm: 0.65mm; AEC Qualified: No
SH-J1 SH-J2 = CMP-0003761-2: Shunt, 2.54mm, Gold, Black; Manufacturer: Wurth Elektronik
TP29-TP32 = CMP-0055137-2: Test Point, Miniature, Red, TH; Manufacturer: Keystone Electronics; Green_REACh: Passed; Green_Lifecycle: Active; ContactFinish: Silver; CNHeader: FALSE; CT: TRUE
TP33 TP34 = CMP-0055138-2: Test Point, Miniature, Black, TH; Manufacturer: Keystone Electronics; ContactFinish: Silver; Green_Lifecycle: Active; Green_REACh: Passed; CNHeader: FALSE; CT: TRUE
U6 = CMP-0091339-1: 300-mA, ultra-low-noise, low-IQ, low-dropout (LDO) linear regulator with high PSRR 5-SOT-23 -40 to 125; Manufacturer: Texas Instruments; TJmax_C: +125°C; Min Supply Voltage: 1.6V; SizeZ_mm: 1.45mm; Output Voltage: 5V; Number Of Outputs: 1; Nominal Supply Current: 6.5uA; AEC Qualified: No; Accuracy Percentage: 1.5%; Max Supply Voltage: 6V; Dropout Voltage: 140mV; Standoff Height: 0mm; Output Type: Fixed
U7 = CMP-0072146-1: Switched Capacitor Voltage Converter, 6-pin SOT-23; Manufacturer: Texas Instruments; PackageTopMarking: S03A*XTT; PowerWise: N; CompType: Switch Caps
U8 = CMP-0093105-2: Buck Converter, Adjustable, 4V-36V Input, 1-28V 1A Output, SOT23-6; Manufacturer: Texas Instruments; SizeZ_mm: 1.45mm; Max Supply Voltage: 36V; Standoff Height: 0mm; Min Supply Voltage: 4V; Number Of Outputs: 1; TJmax_C: +150°C; Nominal Supply Current: 80uA; Max Duty Cycle: 98%; CompType: IC; Switching Frequency: 700kHz; AEC Qualified: No; Output Type: AdjustableProgrammable; AEC Category: Q200
U9 = CMP-0092532-1: 300-mA, Ultra-Low-Noise, Low-IQ, High PSRR LDO; Manufacturer: Texas Instruments; TJmax_C: +125°C; Min Supply Voltage: 1.6V; SizeZ_mm: 1.45mm; Output Voltage: 3.3V; Number Of Outputs: 1; Nominal Supply Current: 6.5uA; AEC Qualified: No; Accuracy Percentage: 1.5%; Max Supply Voltage: 6V; Dropout Voltage: 145mV; Standoff Height: 0mm; Output Type: Fixed
U10 = CMP-0095212-1: Linear Voltage Regulator IC Positive Fixed 1 Output 300mA SOT-23-5; Manufacturer: Texas Instruments; TJmax_C: +125°C; Max Supply Voltage: 6V; SizeZ_mm: 1.45mm; Accuracy Percentage: 1.5%; AEC Qualified: No; Standoff Height: 0mm; Output Voltage: 1.8V; Min Supply Voltage: 1.6V; Nominal Supply Current: 6.5-2000uA; Dropout Voltage: 690mV; Number Of Outputs: 1

## Sheet DC431_Hardware.SchDoc
size 431 x 279 mm; Date: Not shown in title block; ApprovedBy: Not shown in title block; CheckedBy: Not shown in title block; Author: Not shown in title block; CompanyName: Not shown in title block; DrawnBy: Battery test; Engineer: Not shown in title block; Organization: Not shown in title block; Address1: Not shown in title block; Address2: Not shown in title block; Address3: Not shown in title block; Address4: Not shown in title block; DocumentNumber: 8; Revision: Use project parameter SCH_Rev; SheetNumber: 9; SheetTotal: 9; PageSetup: Record=PageOptions¦CenterHorizontal=True¦CenterVertical=True¦PrintScale=1.00¦XCorrection=1.00¦YCorrection=1.00¦PrintKind=0¦BorderSize=5000000¦LeftOffset=0¦BottomOffset=0¦Orientation=2¦PaperLength=1000¦PaperWidth=1000¦Scale=100¦PaperSource=15¦PrintQuality=600¦MediaType=1¦DitherType=10¦PaperKind=Letter¦PrintScaleMode=1
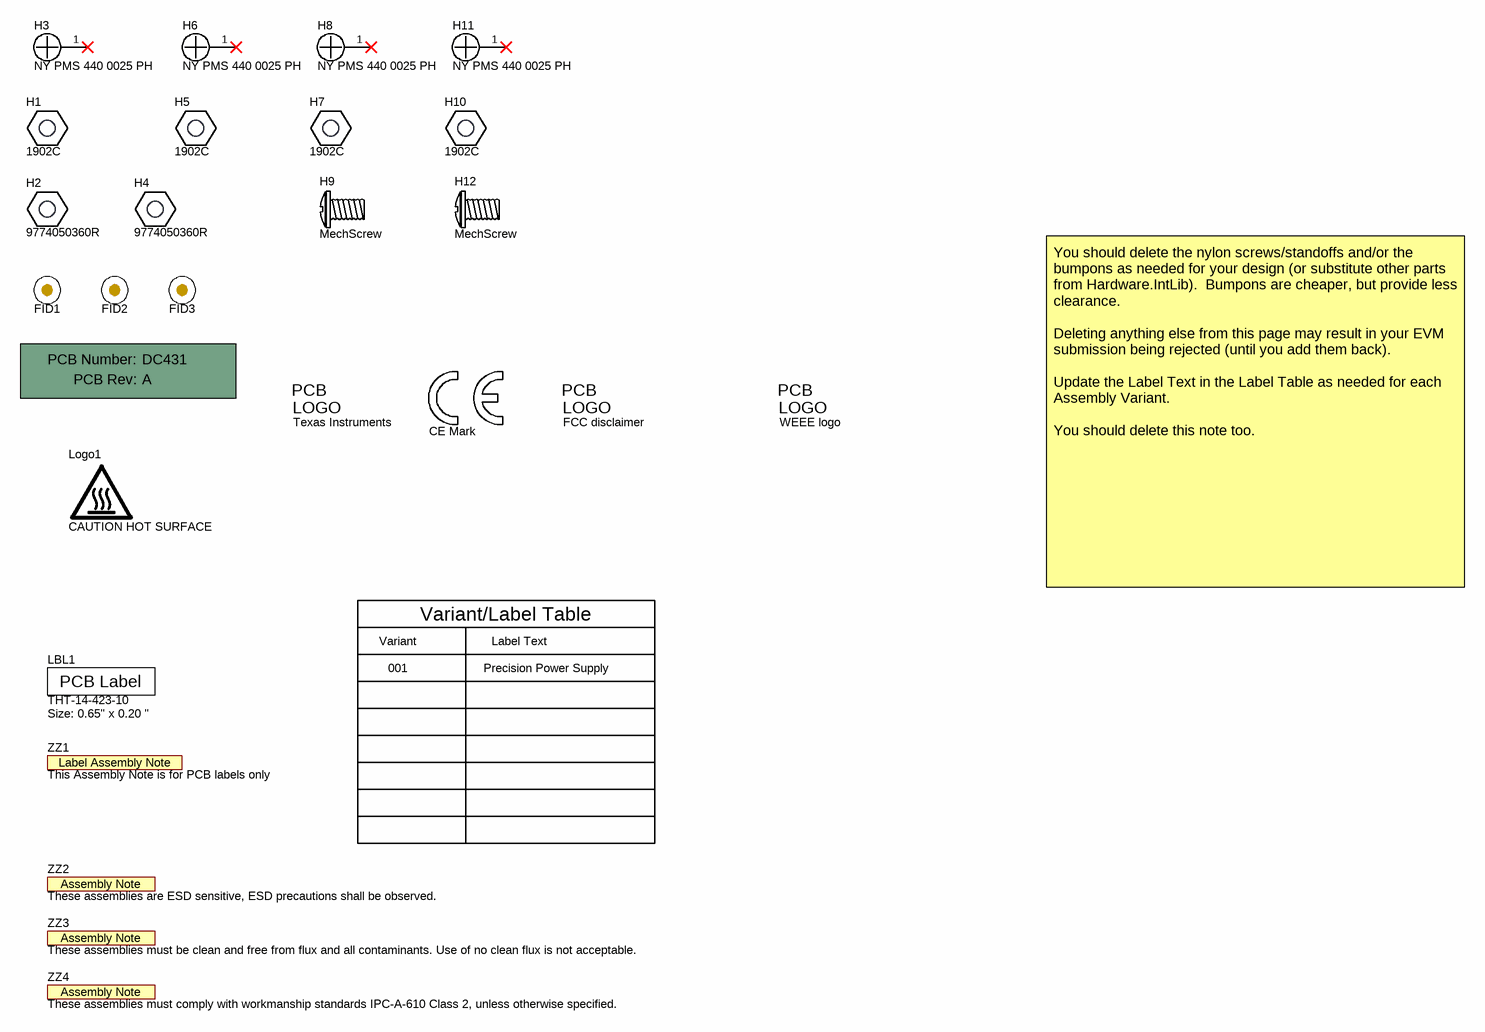
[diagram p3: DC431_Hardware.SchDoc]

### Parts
!PCB1  Printed Circuit Board  (value not drawn)  (mechanical)
FID1  Fiducial  [Fiducial10-20]  (value not drawn)
FID2  Fiducial  [Fiducial10-20]  (value not drawn)
FID3  Fiducial  [Fiducial10-20]  (value not drawn)
H1  1902C  [Keystone_1902C]
H2  9774050360R  [Wurth_WA-SMSI]
H3  NY PMS 440 0025 PH  [NY PMS 440 0025 PH]
H4  9774050360R  [Wurth_WA-SMSI]
H5  1902C  [Keystone_1902C]
H6  NY PMS 440 0025 PH  [NY PMS 440 0025 PH]
H7  1902C  [Keystone_1902C]
H8  NY PMS 440 0025 PH  [NY PMS 440 0025 PH]
H9  MechScrew  (mechanical)
H10  1902C  [Keystone_1902C]
H11  NY PMS 440 0025 PH  [NY PMS 440 0025 PH]
H12  MechScrew  (mechanical)
LBL1  THT-14-423-10  Note: Size: 0.65" x 0.20 "  [Label_650x200]
Logo1  CAUTION HOT SURFACE  [IEC_HotSurface_Medium]  (no BOM)
Logo2  Texas Instruments  [TI_Stacked_Overlay_Small]  (no BOM)
Logo3  CE Mark  [CE_Mark_5mm]  (no BOM)
Logo4  FCC disclaimer  [FCC_disclaimer]  (no BOM)
Logo5  WEEE logo  [WEEE_Minimum]  (no BOM)
ZZ1  This Assembly Note is for PCB labels only  [AssemblyNoteLabel]  (no BOM)
ZZ2  These assemblies are ESD sensitive, ESD precautions shall be observed.  [AssemblyNote]  (no BOM)
ZZ3  These assemblies must be clean and free from flux and all contaminants. Use of no clean flux is not acceptable.  [AssemblyNote]  (no BOM)
ZZ4  These assemblies must comply with workmanship standards IPC-A-610 Class 2, unless otherwise specified.  [AssemblyNote]  (no BOM)

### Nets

Not connected (* = marked no-connect by the designer): H3 1*; H6 1*; H8 1*; H11 1*

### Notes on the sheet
- Variant
- Variant/Label Table
- Label Text
- You should delete the nylon screws/standoffs and/or the bumpons as needed for your design (or substitute other parts from Hardware.IntLib).  Bumpons are cheaper, but provide less clearance.
  Deleting anything else from this page may result in your EVM submission being rejected (until you add them back).
  Update the Label Text in the Label Table as needed for each Assembly Variant.
  You should delete this note too.
- 001
- Precision Power Supply

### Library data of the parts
!PCB1 = CMP-0003618-2: Manufacturer: Any; PartNumber: DC431
FID1-FID3 = CMP-0077181-1: Fiducial mark.  There is nothing to buy or mount.
H1 H5 H7 H10 = CMP-0003610-1: Standoff, Hex, 0.5"L #4-40 Nylon; Manufacturer: Keystone; CompType: Hardware
H2 H4 = CMP-0003785-1: ROUND STANDOFF M3 STEEL 5MM; Manufacturer: Wurth Elektronik
H3 H6 H8 H11 = CMP-0003617-1: Machine Screw, Round, #4-40 x 1/4, Nylon, Philips panhead; Manufacturer: B&F Fastener Supply; CompType: Hardware
H9 H12 = CMP-0003767-1: Machine Screw Pan PHILLIPS M3; Manufacturer: APM HEXSEAL; PartNumber: RM3X4MM 2701; CompType: Standoff
LBL1 = CMP-0003625-1: Thermal Transfer Printable Labels, 0.650" W x 0.200" H - 10,000 per roll; Manufacturer: Brady; CompType: Label
Logo1 = CMP-0074837-2: IEC 61010-1 Hot Surface Warning; Manufacturer: Texas Instruments; CompType: IC; AEC Category: Q200; SymbolCreator: a0412235
Logo2 = CMP-0074838-1: Texas Instrument Corporate Signature; SymbolCreator: a0412235; Lib Reference: TI_Logo; Library Reference: Logo
Logo3 = CMP-0074844-1: SymbolCreator: a0412235
Logo4 = CMP-0074847-1: FCC_disclaimer; Library Reference: Logo
Logo5 = CMP-0074769-3: Manufacturer: Texas Instruments; CompType: IC; AEC Category: Q200
ZZ1 = CMP-0003616-3
ZZ2 = CMP-0077236-1
ZZ3 = CMP-0077237-1
ZZ4 = CMP-0077238-1

## Sheet DC431_Relay.SchDoc
size 431 x 279 mm; Date: Not shown in title block; ApprovedBy: Not shown in title block; CheckedBy: Not shown in title block; Author: Not shown in title block; CompanyName: Not shown in title block; DrawnBy: Battery test; Engineer: Not shown in title block; Organization: Not shown in title block; Address1: Not shown in title block; Address2: Not shown in title block; Address3: Not shown in title block; Address4: Not shown in title block; DocumentNumber: 3; Revision: Use project parameter SCH_Rev; SheetNumber: 4; SheetTotal: 9; PageSetup: Record=PageOptions¦CenterHorizontal=True¦CenterVertical=True¦PrintScale=1.00¦XCorrection=1.00¦YCorrection=1.00¦PrintKind=0¦BorderSize=5000000¦LeftOffset=0¦BottomOffset=0¦Orientation=2¦PaperLength=1000¦PaperWidth=1000¦Scale=100¦PaperSource=15¦PrintQuality=600¦MediaType=1¦DitherType=10¦PaperKind=Letter¦PrintScaleMode=1
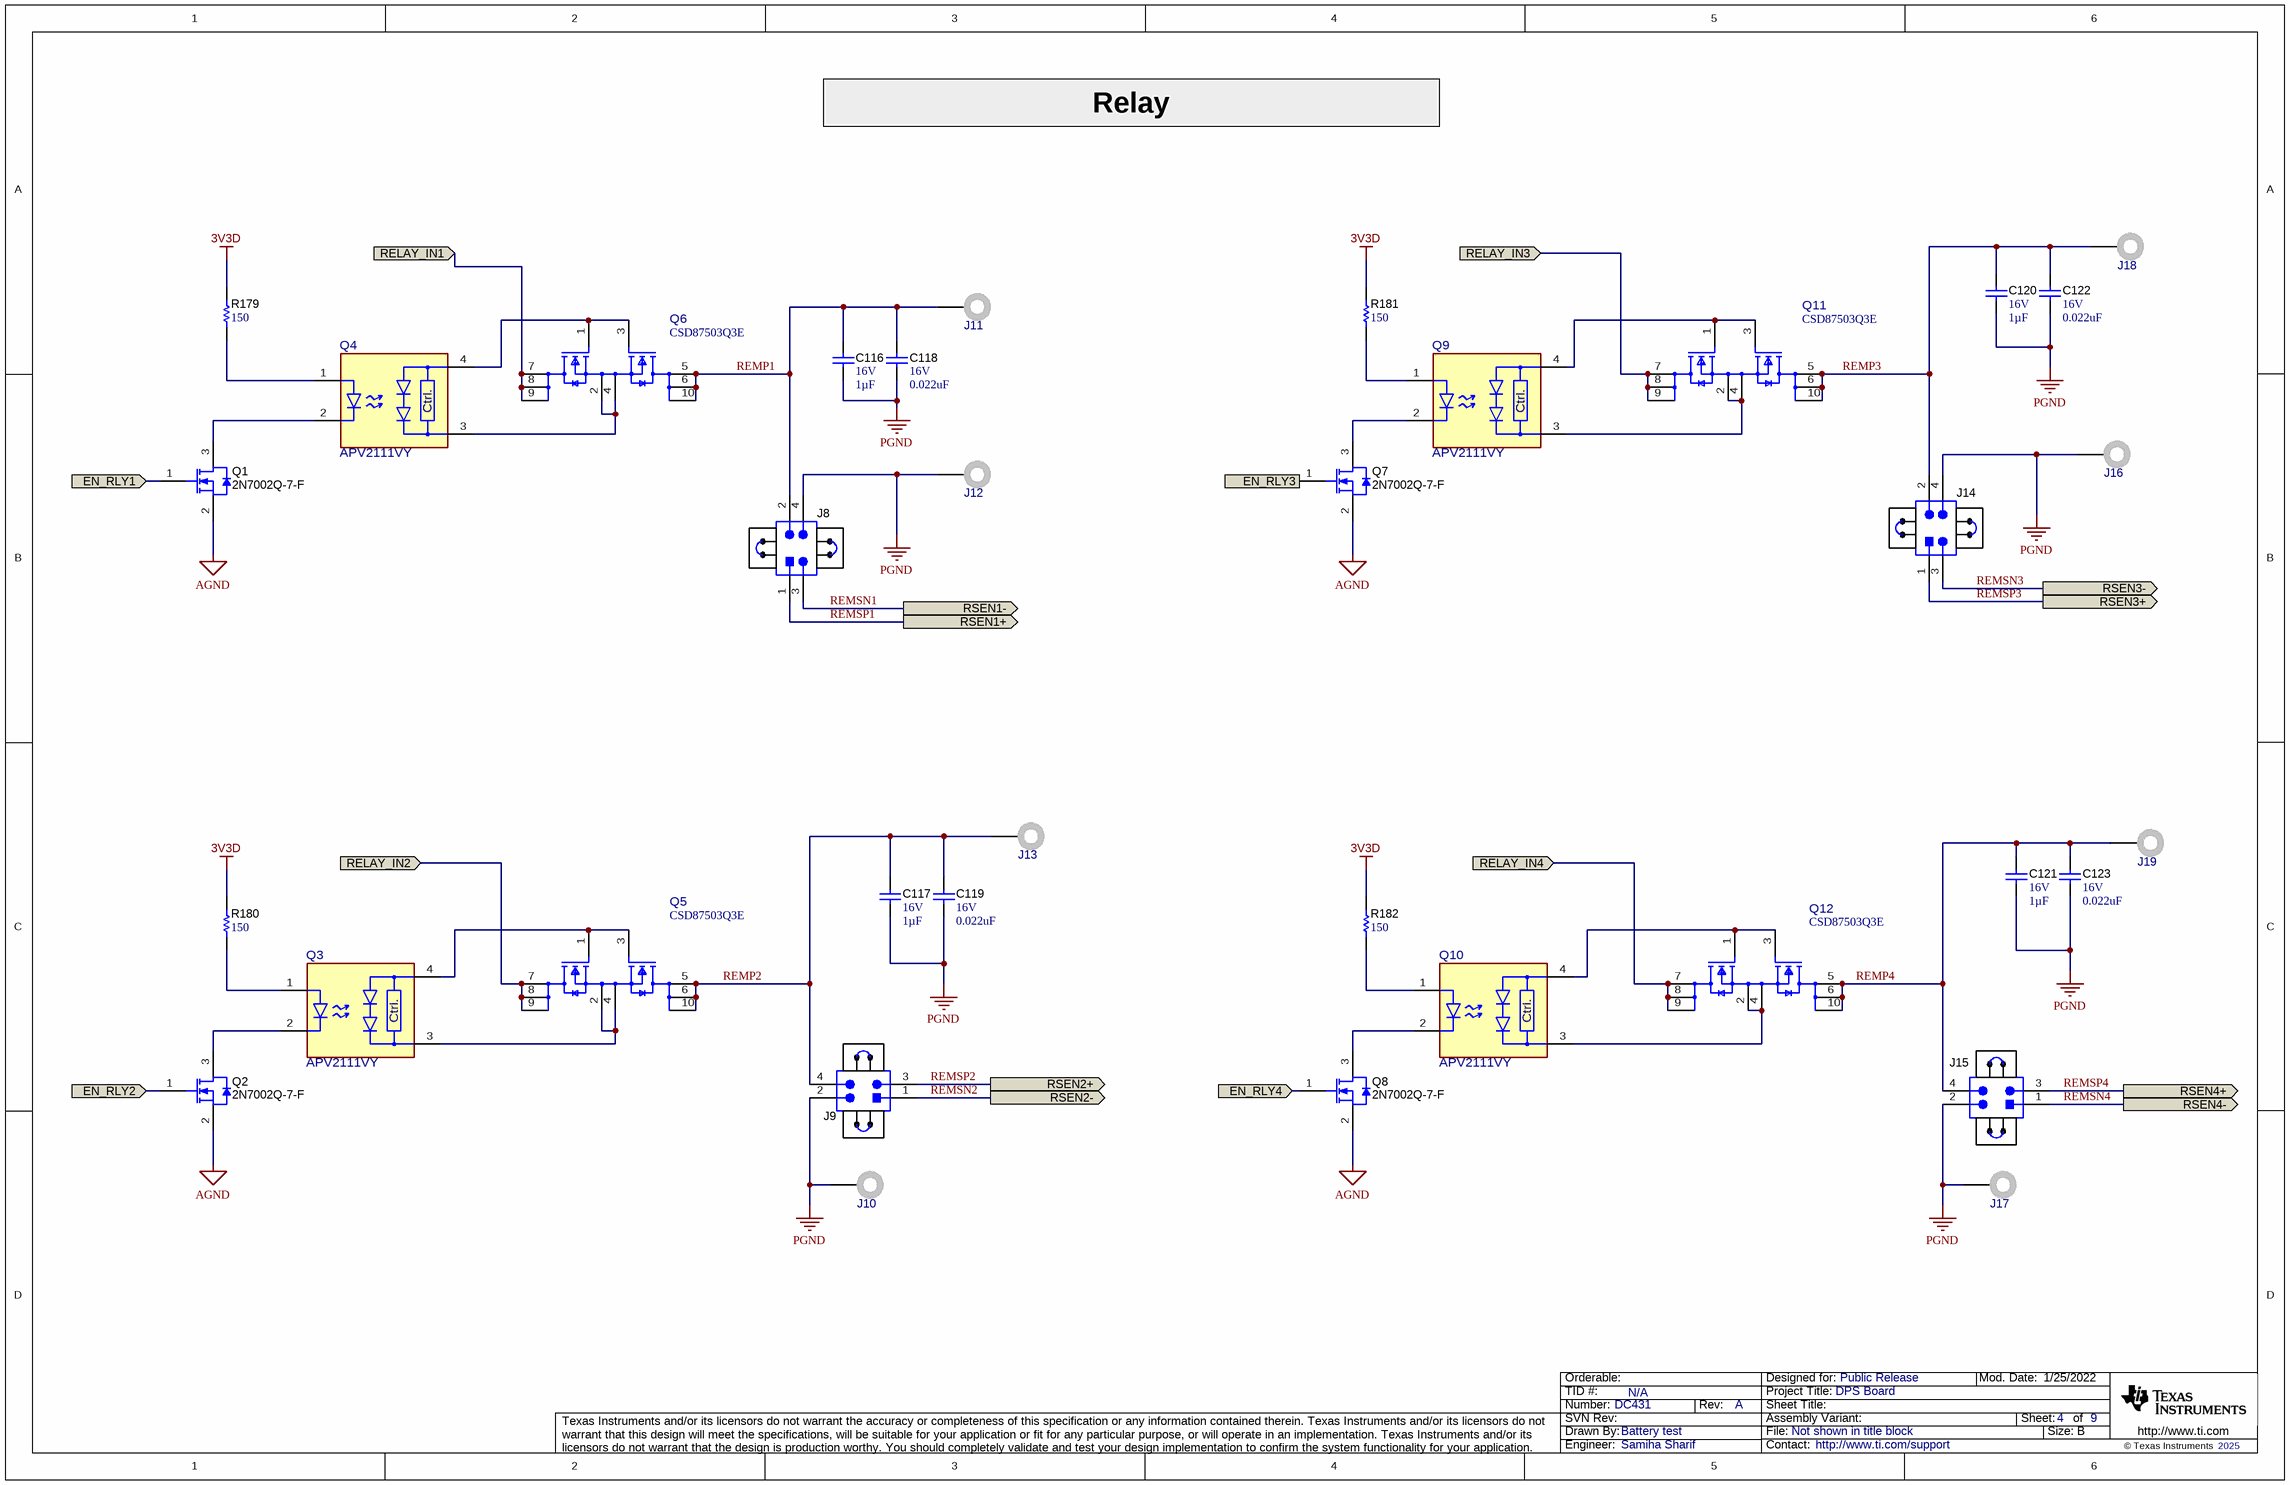
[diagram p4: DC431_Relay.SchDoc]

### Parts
C116  VDC_V: 16V  ValueDisplayed: 1µF  [0603S]  (hidden comment: CL10B105KO8VPNC)
C117  VDC_V: 16V  ValueDisplayed: 1µF  [0603S]  (hidden comment: CL10B105KO8VPNC)
C118  VDC_V: 16V  ValueDisplayed: 0.022uF  [0603S]  (hidden comment: GRM188R71C223KA01D)
C119  VDC_V: 16V  ValueDisplayed: 0.022uF  [0603S]  (hidden comment: GRM188R71C223KA01D)
C120  VDC_V: 16V  ValueDisplayed: 1µF  [0603S]  (hidden comment: CL10B105KO8VPNC)
C121  VDC_V: 16V  ValueDisplayed: 1µF  [0603S]  (hidden comment: CL10B105KO8VPNC)
C122  VDC_V: 16V  ValueDisplayed: 0.022uF  [0603S]  (hidden comment: GRM188R71C223KA01D)
C123  VDC_V: 16V  ValueDisplayed: 0.022uF  [0603S]  (hidden comment: GRM188R71C223KA01D)
J8  TSW-102-07-G-D  [TSW-102-07-G-D]  (value not drawn)
J9  TSW-102-07-G-D  [TSW-102-07-G-D]  (value not drawn)
J10  CMP-0055165-2  [Keystone_575-4]  (value not drawn)
J11  CMP-0055165-2  [Keystone_575-4]  (value not drawn)
J12  CMP-0055165-2  [Keystone_575-4]  (value not drawn)
J13  CMP-0055165-2  [Keystone_575-4]  (value not drawn)
J14  TSW-102-07-G-D  [TSW-102-07-G-D]  (value not drawn)
J15  TSW-102-07-G-D  [TSW-102-07-G-D]  (value not drawn)
J16  CMP-0055165-2  [Keystone_575-4]  (value not drawn)
J17  CMP-0055165-2  [Keystone_575-4]  (value not drawn)
J18  CMP-0055165-2  [Keystone_575-4]  (value not drawn)
J19  CMP-0055165-2  [Keystone_575-4]  (value not drawn)
Q1  2N7002Q-7-F  [SOT-23]
Q2  2N7002Q-7-F  [SOT-23]
Q3  APV2111VY  [FP-APV2111VY_SSOP4-MFG]
Q4  APV2111VY  [FP-APV2111VY_SSOP4-MFG]
Q5  CSD87503Q3E  [DTD0008A-MFG]
Q6  CSD87503Q3E  [DTD0008A-MFG]
Q7  2N7002Q-7-F  [SOT-23]
Q8  2N7002Q-7-F  [SOT-23]
Q9  APV2111VY  [FP-APV2111VY_SSOP4-MFG]
Q10  APV2111VY  [FP-APV2111VY_SSOP4-MFG]
Q11  CSD87503Q3E  [DTD0008A-MFG]
Q12  CSD87503Q3E  [DTD0008A-MFG]
R179  ValueDisplayed: 150  [0402S]  (hidden comment: CRCW0402150RFKED)
R180  ValueDisplayed: 150  [0402S]  (hidden comment: CRCW0402150RFKED)
R181  ValueDisplayed: 150  [0402S]  (hidden comment: CRCW0402150RFKED)
R182  ValueDisplayed: 150  [0402S]  (hidden comment: CRCW0402150RFKED)
SH-J3  60900213421  [Wurth_60900213421]  (value not drawn)
SH-J4  60900213421  [Wurth_60900213421]  (value not drawn)
SH-J5  60900213421  [Wurth_60900213421]  (value not drawn)
SH-J6  60900213421  [Wurth_60900213421]  (value not drawn)
SH-J7  60900213421  [Wurth_60900213421]  (value not drawn)
SH-J8  60900213421  [Wurth_60900213421]  (value not drawn)
SH-J9  60900213421  [Wurth_60900213421]  (value not drawn)
SH-J10  60900213421  [Wurth_60900213421]  (value not drawn)

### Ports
EN_RLY1 (in), EN_RLY2 (in), EN_RLY3 (in), EN_RLY4 (in), RELAY_IN1 (in), RELAY_IN2 (in), RELAY_IN3 (in), RELAY_IN4 (in), RSEN1+ (out), RSEN1- (out), RSEN2+ (out), RSEN2- (out), RSEN3+ (out), RSEN3- (out), RSEN4+ (out), RSEN4- (out)

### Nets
3V3D: R179.2 R180.2 R181.2 R182.2
AGND: Q1.2(S) Q2.2(S) Q7.2(S) Q8.2(S)
PGND: C116.2 C117.2 C118.2 C119.2 C120.2 C121.2 C122.2 C123.2 J8.4 J9.2 J10.1 J12.1 J14.4 J15.2 J16.1 J17.1
EN_RLY1: Q1.1(G) ; port EN_RLY1
EN_RLY2: Q2.1(G) ; port EN_RLY2
EN_RLY3: Q7.1(G) ; port EN_RLY3
EN_RLY4: Q8.1(G) ; port EN_RLY4
RELAY_IN1: Q6.7(Drain1) Q6.8(Drain1) Q6.9(Drain1) ; port RELAY_IN1
RELAY_IN2: Q5.7(Drain1) Q5.8(Drain1) Q5.9(Drain1) ; port RELAY_IN2
RELAY_IN3: Q11.7(Drain1) Q11.8(Drain1) Q11.9(Drain1) ; port RELAY_IN3
RELAY_IN4: Q12.7(Drain1) Q12.8(Drain1) Q12.9(Drain1) ; port RELAY_IN4
REMP1: C116.1 C118.1 J8.2 J11.1 Q6.5(Drain2) Q6.6(Drain2) Q6.10(Drain2)
REMP2: C117.1 C119.1 J9.4 J13.1 Q5.5(Drain2) Q5.6(Drain2) Q5.10(Drain2)
REMP3: C120.1 C122.1 J14.2 J18.1 Q11.5(Drain2) Q11.6(Drain2) Q11.10(Drain2)
REMP4: C121.1 C123.1 J15.4 J19.1 Q12.5(Drain2) Q12.6(Drain2) Q12.10(Drain2)
REMSN1: J8.3 ; port RSEN1-  [project net AINM1]
REMSN2: J9.1 ; port RSEN2-  [project net AINM2]
REMSN3: J14.3 ; port RSEN3-  [project net AINM3]
REMSN4: J15.1 ; port RSEN4-
REMSP1: J8.1 ; port RSEN1+  [project net AINP1]
REMSP2: J9.3 ; port RSEN2+  [project net AINP2]
REMSP3: J14.1 ; port RSEN3+  [project net AINP3]
REMSP4: J15.3 ; port RSEN4+
NetQ1_3: Q1.3(D) Q4.2(CATHODE)
NetQ2_3: Q2.3(D) Q3.2(CATHODE)
NetQ3_1: Q3.1(ANODE) R180.1
NetQ3_3: Q3.3(-) Q5.2(Source1) Q5.4(Source2)
NetQ3_4: Q3.4(+) Q5.1(Gate1) Q5.3(Gate2)
NetQ4_1: Q4.1(ANODE) R179.1
NetQ4_3: Q4.3(-) Q6.2(Source1) Q6.4(Source2)
NetQ4_4: Q4.4(+) Q6.1(Gate1) Q6.3(Gate2)
NetQ7_3: Q7.3(D) Q9.2(CATHODE)
NetQ8_3: Q8.3(D) Q10.2(CATHODE)
NetQ9_1: Q9.1(ANODE) R181.1
NetQ9_3: Q9.3(-) Q11.2(Source1) Q11.4(Source2)
NetQ9_4: Q9.4(+) Q11.1(Gate1) Q11.3(Gate2)
NetQ10_1: Q10.1(ANODE) R182.1
NetQ10_3: Q10.3(-) Q12.2(Source1) Q12.4(Source2)
NetQ10_4: Q10.4(+) Q12.1(Gate1) Q12.3(Gate2)

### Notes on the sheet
- Relay

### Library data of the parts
C116 C117 C120 C121 = CMP-0085302-1: CAP, CERM, 1 µF, 16 V,+/- 10%, X7R, AEC-Q200 Grade 1, 0603; Manufacturer: Samsung Electro-Mechanics; TaMin_C: -55°C; Polarized: N; SizeAreaWB_mm2: 4.68; U/M: EA; Value: 1uF; TaMax_C: 125°C; SizeZ_mm: 1; SizeX_mm: 1.6; SizeY_mm: 0.8; Cap_Case: 0603; SizeArea_mm2: 1.28; AEC Qualified: Y; AEC Category: Q200
C118 C119 C122 C123 = CMP-0007388-4: CAP, CERM, 0.022 uF, 16 V, +/- 10%, X7R, 0603; Manufacturer: MuRata; TaMin_C: -55°C; Polarized: N; SizeAreaWB_mm2: 4.68; Value1: Unknown; U/M: EA; TaMax_C: 125°C; SizeZ_mm: 1; SizeX_mm: 1.6; SizeY_mm: 0.8; Cap_Case: 0603; SizeArea_mm2: 1.28; Cap_F: 22nF; AEC Category: Q200
J8 J9 J14 J15 = CMP-0075404-1: Header, 100mil, 2x2, Gold, TH; Manufacturer: Samtec; CNHeader: True; CT: False; Cert_CSA: Y; Cert_CULUS: N; Current_A: 6.3A; Gender: Male; Green_Lifecycle: Active; Green_REACh: Passed; Pitch_mm: 2.54; Row_Count: 2; Voltage_V: 550V
J10-J13 J16-J19 = CMP-0055165-2: as J21 on sheet DC431_TopLevel
Q1 Q2 Q7 Q8 = CMP-0085603-1: MOSFET, N-CH, 60 V, 0.115 A, AEC-Q101, SOT-23; Manufacturer: Diodes Inc.; Alternate Manufacturer: None; SizeAreaWB_mm2: 14; Value: 60V; QgTyp_nC: 0.223; IdsMax_A: 115mA; AEC Category: Q101; SizeY_mm: 3; SizeArea_mm2: 7.5; SizeX_mm: 2.5; SizeZ_mm: 1.1; Value1: ? ohm; ChMode: Enhancement; Vgs_V: 20V; ChType: N; AEC Qualified: Y; Value2: 0.223 nC
Q3 Q4 Q9 Q10 = CMP-0126605-1: Optoisolator Photovoltaic Output 1500Vrms 1 Channel 4-SSOP; Manufacturer: Panasonic; SizeZ_mm: 1.9mm; Voltage_Isolation_Vrms: 1.5kV; AEC Qualified: No; Forward Current: 50mA; Power_TotalModule: 75mW; TaMax_C: +85°C; TaMin_C: -40°C; TJmax_C: +125°C; Vr_V: 5V
Q5 Q6 Q11 Q12 = CMP-0127063-1: NexFET Power MOSFET Dual N-Channel 30V 10A 8-Pin VSON T/R; Manufacturer: Texas Instruments; AEC Qualified: No; QgTyp_nC: 32.9nC @ 10V; Rdson45_ohm: 13.5m; SizeZ_mm: 1mm; VdsMax_V: 950mV; Vgs_V: 20V; Input Capacitance At Vds: 782pF @ 15V; Number Of Channels: 2; Power_W: 2.6W; Pulse Drain Current: 89A; Reverse Recovery Charge: 9.2nC; Reverse Recovery Time: 14ns; Rthja Max: 60°C/W; Standoff Height: 0mm; Threshold Vgs Max: 2.1V; Threshold Vgs Min: 1.3V; TJmax_C: +150°C; Transconductance: 24S; Turn Off Delay Time: 25ns; Turn On Delay Time: 10ns; Typ Forward Diode Voltage: 0.75V
R179-R182 = CMP-0026022-3: RES, 150, 1%, 0.063 W, AEC-Q200 Grade 0, 0402; Manufacturer: Vishay-Dale; Power_W: 63mW; TempCo: 100 ppm/C; Value_Code: 150R; Value: 150; EIA_Code: E96; SizeX_mm: 1; SizeY_mm: 0.5; SizeZ_mm: 0.6; Value2: 0.063W; AEC Qualified: Y; VDC_V: 50V; AEC Category: Q200; AEC Grade: 0
SH-J3-SH-J10 = CMP-0003761-2: as SH-J1 on sheet DC431_BiasPower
